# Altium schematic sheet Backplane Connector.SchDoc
size A
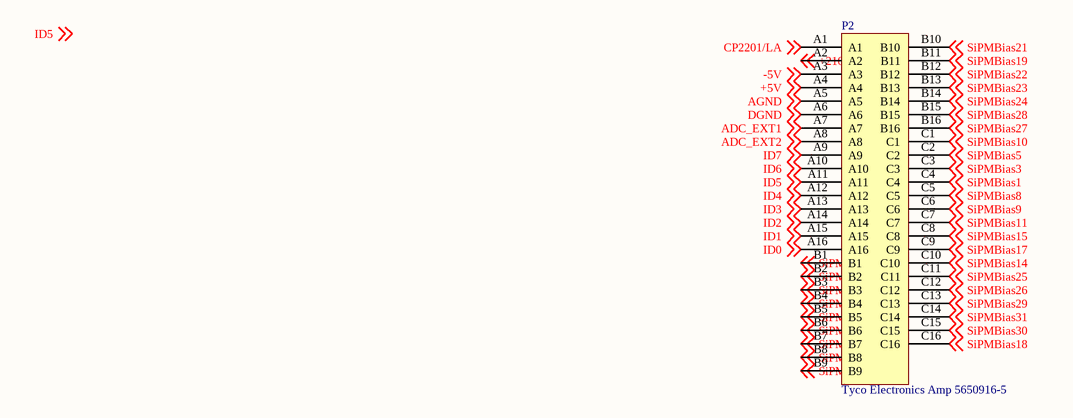
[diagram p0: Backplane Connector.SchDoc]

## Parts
P2  Tyco Electronics Amp 5650916-5  [EURO2.54-2H48]

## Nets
+5V: P2.A4 ; off-sheet +5V
+210V: P2.A2 ; off-sheet +210V
-5V: P2.A3 ; off-sheet -5V
ADC_EXT1: P2.A7 ; off-sheet ADC_EXT1
ADC_EXT2: P2.A8 ; off-sheet ADC_EXT2
AGND: P2.A5 ; off-sheet AGND
CP2201/LA: P2.A1 ; off-sheet CP2201/LA
DGND: P2.A6 ; off-sheet DGND
ID0: P2.A16 ; off-sheet ID0
ID1: P2.A15 ; off-sheet ID1
ID2: P2.A14 ; off-sheet ID2
ID3: P2.A13 ; off-sheet ID3
ID4: P2.A12 ; off-sheet ID4
ID5: P2.A11 ; off-sheet ID5
ID6: P2.A10 ; off-sheet ID6
ID7: P2.A9 ; off-sheet ID7
SiPMBias0: P2.B3 ; off-sheet SiPMBias0
SiPMBias1: P2.C4 ; off-sheet SiPMBias1
SiPMBias2: P2.B2 ; off-sheet SiPMBias2
SiPMBias3: P2.C3 ; off-sheet SiPMBias3
SiPMBias4: P2.B4 ; off-sheet SiPMBias4
SiPMBias5: P2.C2 ; off-sheet SiPMBias5
SiPMBias6: P2.B1 ; off-sheet SiPMBias6
SiPMBias7: P2.B5 ; off-sheet SiPMBias7
SiPMBias8: P2.C5 ; off-sheet SiPMBias8
SiPMBias9: P2.C6 ; off-sheet SiPMBias9
SiPMBias10: P2.C1 ; off-sheet SiPMBias10
SiPMBias11: P2.C7 ; off-sheet SiPMBias11
SiPMBias12: P2.B6 ; off-sheet SiPMBias12
SiPMBias13: P2.B7 ; off-sheet SiPMBias13
SiPMBias14: P2.C10 ; off-sheet SiPMBias14
SiPMBias15: P2.C8 ; off-sheet SiPMBias15
SiPMBias16: P2.B8 ; off-sheet SiPMBias16
SiPMBias17: P2.C9 ; off-sheet SiPMBias17
SiPMBias18: P2.C16 ; off-sheet SiPMBias18
SiPMBias19: P2.B11 ; off-sheet SiPMBias19
SiPMBias20: P2.B9 ; off-sheet SiPMBias20
SiPMBias21: P2.B10 ; off-sheet SiPMBias21
SiPMBias22: P2.B12 ; off-sheet SiPMBias22
SiPMBias23: P2.B13 ; off-sheet SiPMBias23
SiPMBias24: P2.B14 ; off-sheet SiPMBias24
SiPMBias25: P2.C11 ; off-sheet SiPMBias25
SiPMBias26: P2.C12 ; off-sheet SiPMBias26
SiPMBias27: P2.B16 ; off-sheet SiPMBias27
SiPMBias28: P2.B15 ; off-sheet SiPMBias28
SiPMBias29: P2.C13 ; off-sheet SiPMBias29
SiPMBias30: P2.C15 ; off-sheet SiPMBias30
SiPMBias31: P2.C14 ; off-sheet SiPMBias31

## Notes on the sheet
- Labels drawn without touching a wire or pin: ID5

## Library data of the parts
P2 = DIN41612 48 Connector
